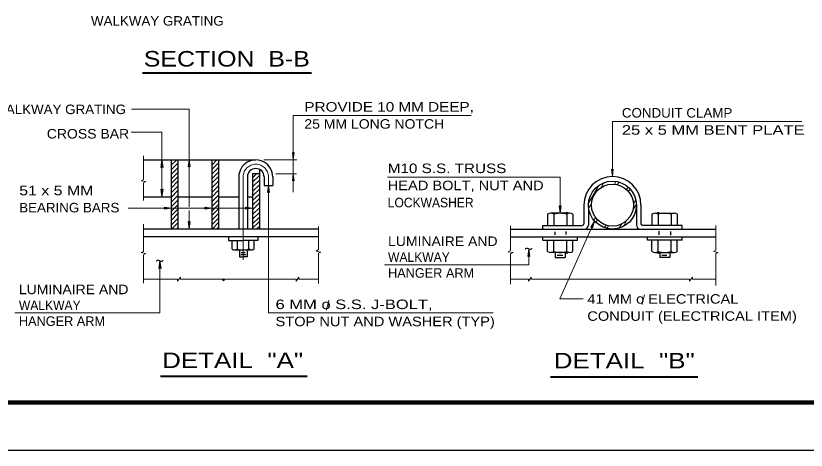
# Model space of a CAD drawing. Extents: x 312601.858 to 312602.699, y 144420.109 to 144420.704.
# Drawn here: x 312602.0138 to 312602.2633, y 144420.1095 to 144420.2465 of the extents above; entities that cross this region are included whole.
import ezdxf
from ezdxf.enums import TextEntityAlignment as Align

# ---------------------------------------------------------------- set-up
doc = ezdxf.new("R2010")
doc.units = 0
doc.header["$LTSCALE"] = 0.0012
doc.header["$PDMODE"] = 32
doc.header["$PDSIZE"] = 0.0006
doc.linetypes.add('DOT_DASHED', pattern=[7.7, 5, -1.2, 0.3, -1.2])
for name, color, linetype, lineweight in [('1', 7, 'Continuous', 13), ('2', 7, 'Continuous', 13), ('39', 7, 'Continuous', 13)]:
    doc.layers.add(name, color=color, linetype=linetype, lineweight=lineweight)

msp = doc.modelspace()

# ---------------------------------------------------------------- hatches: boundary and pattern name
at = {"layer": '39'}
for points in [[(312602.0599, 144420.1989), (312602.0596, 144420.1987), (312602.0599, 144420.2011), (312602.0603, 144420.1987)], [(312602.0599, 144420.1916), (312602.0603, 144420.1918), (312602.0599, 144420.1894), (312602.0596, 144420.1918)], [(312602.1757, 144420.1708), (312602.1754, 144420.1706), (312602.1757, 144420.173), (312602.1761, 144420.1706)], [(312602.1757, 144420.1708), (312602.1754, 144420.1706), (312602.1757, 144420.173), (312602.1761, 144420.1706)], [(312602.1757, 144420.1708), (312602.1754, 144420.1706), (312602.1757, 144420.173), (312602.1761, 144420.1706)], [(312602.0593, 144420.167), (312602.059, 144420.1668), (312602.0593, 144420.1692), (312602.0597, 144420.1668)]]:
    msp.add_hatch(color=256, dxfattribs=at).paths.add_polyline_path(points)

# ---------------------------------------------------------------- linework, layer by layer
at = {"layer": '1'}
for p, q in [((312602.0685, 144420.2171), (312602.0503, 144420.2171)), ((312602.1575, 144420.2151), (312602.1014, 144420.2151)), ((312602.2021, 144420.2132), (312602.2021, 144420.1958)), ((312602.2021, 144420.2132), (312602.2619, 144420.2132)), ((312602.0502, 144420.2098), (312602.0599, 144420.2098)), ((312602.0541, 144420.2023), (312602.0541, 144420.1949)), ((312602.0629, 144420.1994), (312602.0646, 144420.2011)), ((312602.0757, 144420.1994), (312602.0773, 144420.2011)), ((312602.0921, 144420.2011), (312602.1025, 144420.2011)), ((312602.0629, 144420.1979), (312602.065, 144420.2)), ((312602.0629, 144420.1965), (312602.065, 144420.1986)), ((312602.0757, 144420.198), (312602.0778, 144420.2001)), ((312602.0757, 144420.1966), (312602.0778, 144420.1987)), ((312602.0629, 144420.195), (312602.065, 144420.1971)), ((312602.0757, 144420.1951), (312602.0778, 144420.1972)), ((312602.0885, 144420.1954), (312602.0899, 144420.1968)), ((312602.0885, 144420.194), (312602.0907, 144420.1961)), ((312602.0959, 144420.1967), (312602.1024, 144420.1967)), ((312602.1014, 144420.1967), (312602.1014, 144420.1909)), ((312602.0534, 144420.1945), (312602.0541, 144420.1949)), ((312602.0534, 144420.1945), (312602.0549, 144420.1942)), ((312602.0541, 144420.1938), (312602.0549, 144420.1942)), ((312602.0541, 144420.1938), (312602.0541, 144420.1882)), ((312602.0629, 144420.1936), (312602.065, 144420.1957)), ((312602.0629, 144420.1921), (312602.065, 144420.1943)), ((312602.0757, 144420.1937), (312602.0778, 144420.1958)), ((312602.0757, 144420.1922), (312602.0778, 144420.1943)), ((312602.0885, 144420.1926), (312602.0907, 144420.1947)), ((312602.1311, 144420.1956), (312602.1856, 144420.1956)), ((312602.1856, 144420.1956), (312602.1856, 144420.1843)), ((312602.1986, 144420.1923), (312602.1994, 144420.1939)), ((312602.2028, 144420.1934), (312602.2033, 144420.1943)), ((312602.2037, 144420.1933), (312602.2042, 144420.1941)), ((312602.0629, 144420.1907), (312602.065, 144420.1928)), ((312602.0629, 144420.1892), (312602.065, 144420.1914)), ((312602.0757, 144420.1908), (312602.0778, 144420.1929)), ((312602.0757, 144420.1893), (312602.0778, 144420.1915)), ((312602.0885, 144420.1911), (312602.0907, 144420.1932)), ((312602.0885, 144420.1897), (312602.0907, 144420.1918)), ((312602.0936, 144420.193), (312602.0936, 144420.1528)), ((312602.1946, 144420.1874), (312602.1978, 144420.193)), ((312602.2066, 144420.1917), (312602.2071, 144420.1925)), ((312602.2072, 144420.1911), (312602.2077, 144420.1919)), ((312602.0629, 144420.1877), (312602.065, 144420.1898)), ((312602.0757, 144420.1878), (312602.0778, 144420.1899)), ((312602.0885, 144420.1882), (312602.0907, 144420.1903)), ((312602.0885, 144420.1868), (312602.0907, 144420.1889)), ((312602.0629, 144420.1863), (312602.065, 144420.1884)), ((312602.0629, 144420.1848), (312602.065, 144420.1869)), ((312602.0757, 144420.1864), (312602.0778, 144420.1885)), ((312602.0757, 144420.1849), (312602.0778, 144420.187)), ((312602.0885, 144420.1853), (312602.0907, 144420.1875)), ((312602.1931, 144420.1868), (312602.1931, 144420.186)), ((312602.1947, 144420.1858), (312602.1955, 144420.1873)), ((312602.2086, 144420.1852), (312602.2097, 144420.1871)), ((312602.2088, 144420.1872), (312602.2095, 144420.1885)), ((312602.2111, 144420.1868), (312602.2111, 144420.186)), ((312602.0493, 144420.1858), (312602.0629, 144420.1858)), ((312602.0629, 144420.1834), (312602.065, 144420.1855)), ((312602.0629, 144420.1819), (312602.065, 144420.1841)), ((312602.0685, 144420.1851), (312602.0685, 144420.1793)), ((312602.0757, 144420.1858), (312602.0885, 144420.1858)), ((312602.0757, 144420.1835), (312602.0778, 144420.1856)), ((312602.0757, 144420.182), (312602.0778, 144420.1841)), ((312602.0885, 144420.1838), (312602.0907, 144420.1859)), ((312602.0885, 144420.1824), (312602.0907, 144420.1845)), ((312602.0629, 144420.1805), (312602.065, 144420.1826)), ((312602.0631, 144420.1793), (312602.065, 144420.1812)), ((312602.0757, 144420.1806), (312602.0778, 144420.1827)), ((312602.076, 144420.1794), (312602.0778, 144420.1813)), ((312602.0885, 144420.1809), (312602.0907, 144420.183)), ((312602.0885, 144420.1795), (312602.0907, 144420.1816)), ((312602.1965, 144420.1817), (312602.1855, 144420.1572)), ((312602.1963, 144420.182), (312602.1968, 144420.1829)), ((312602.1969, 144420.1814), (312602.1974, 144420.1822)), ((312602.2056, 144420.1801), (312602.2067, 144420.182)), ((312602.0541, 144420.1808), (312602.0541, 144420.1722)), ((312602.0646, 144420.1793), (312602.065, 144420.1797)), ((312602.0774, 144420.1794), (312602.0778, 144420.1798)), ((312602.0898, 144420.1793), (312602.0907, 144420.1801)), ((312602.1094, 144420.1801), (312602.1094, 144420.1728)), ((312602.17, 144420.1803), (312602.17, 144420.1725)), ((312602.1816, 144420.1804), (312602.1856, 144420.1804)), ((312602.1896, 144420.1804), (312602.1875, 144420.1804)), ((312602.1996, 144420.1797), (312602.2001, 144420.1805)), ((312602.2004, 144420.1794), (312602.2009, 144420.1803)), ((312602.2043, 144420.1796), (312602.2051, 144420.1809)), ((312602.2101, 144420.1792), (312602.2088, 144420.1792)), ((312602.2169, 144420.1792), (312602.211, 144420.1792)), ((312602.2146, 144420.1804), (312602.2186, 144420.1804)), ((312602.2204, 144420.1792), (312602.2168, 144420.1792)), ((312602.2226, 144420.1804), (312602.2186, 144420.1804)), ((312602.2348, 144420.1804), (312602.2348, 144420.1726)), ((312602.0821, 144420.1756), (312602.0856, 144420.1756)), ((312602.0891, 144420.1756), (312602.0856, 144420.1756)), ((312602.1816, 144420.1757), (312602.1856, 144420.1757)), ((312602.1896, 144420.1757), (312602.1856, 144420.1757)), ((312602.2146, 144420.1757), (312602.2186, 144420.1757)), ((312602.2226, 144420.1757), (312602.2186, 144420.1757)), ((312602.0534, 144420.1718), (312602.0541, 144420.1722)), ((312602.0534, 144420.1718), (312602.0549, 144420.1715)), ((312602.0541, 144420.1711), (312602.0549, 144420.1715)), ((312602.0541, 144420.1711), (312602.0541, 144420.1622)), ((312602.1086, 144420.1723), (312602.1094, 144420.1728)), ((312602.1086, 144420.1723), (312602.1101, 144420.172)), ((312602.1094, 144420.1716), (312602.1101, 144420.172)), ((312602.1094, 144420.1716), (312602.1094, 144420.1621)), ((312602.1692, 144420.1721), (312602.17, 144420.1725)), ((312602.1692, 144420.1721), (312602.1708, 144420.1718)), ((312602.17, 144420.1714), (312602.1708, 144420.1718)), ((312602.17, 144420.1714), (312602.17, 144420.1619)), ((312602.1757, 144420.173), (312602.1757, 144420.168)), ((312602.234, 144420.1722), (312602.2348, 144420.1726)), ((312602.234, 144420.1722), (312602.2355, 144420.1718)), ((312602.2348, 144420.1715), (312602.2355, 144420.1718)), ((312602.2348, 144420.1715), (312602.2348, 144420.1614)), ((312602.0593, 144420.1692), (312602.0593, 144420.1528)), ((312602.1302, 144420.168), (312602.1757, 144420.168)), ((312602.0649, 144420.1628), (312602.0658, 144420.1641)), ((312602.0658, 144420.1634), (312602.0658, 144420.1641)), ((312602.1023, 144420.1628), (312602.1032, 144420.1641)), ((312602.1032, 144420.1634), (312602.1032, 144420.1641)), ((312602.1756, 144420.1628), (312602.1765, 144420.1641)), ((312602.1765, 144420.1634), (312602.1765, 144420.1641)), ((312602.2264, 144420.1628), (312602.2274, 144420.1641)), ((312602.2274, 144420.1634), (312602.2274, 144420.1641)), ((312602.0541, 144420.1634), (312602.0649, 144420.1634)), ((312602.0649, 144420.1628), (312602.0649, 144420.1634)), ((312602.0658, 144420.1634), (312602.1023, 144420.1634)), ((312602.1023, 144420.1628), (312602.1023, 144420.1634)), ((312602.1032, 144420.1634), (312602.1094, 144420.1634)), ((312602.17, 144420.1634), (312602.1756, 144420.1634)), ((312602.1756, 144420.1628), (312602.1756, 144420.1634)), ((312602.1765, 144420.1634), (312602.2264, 144420.1634)), ((312602.2264, 144420.1628), (312602.2264, 144420.1634)), ((312602.2274, 144420.1634), (312602.2348, 144420.1634)), ((312602.1929, 144420.1572), (312602.1855, 144420.1572)), ((312602.0593, 144420.1528), (312602.0135, 144420.1528)), ((312602.1645, 144420.1528), (312602.0936, 144420.1528))]:
    msp.add_line(p, q, dxfattribs=at)
at = {"layer": '1', "lineweight": 25}
for p, q in [((312602.0541, 144420.2011), (312602.0896, 144420.2011)), ((312602.0629, 144420.2011), (312602.0629, 144420.1793)), ((312602.065, 144420.2011), (312602.065, 144420.1793)), ((312602.0757, 144420.2011), (312602.0757, 144420.1794)), ((312602.0778, 144420.2011), (312602.0778, 144420.1794)), ((312602.0885, 144420.1968), (312602.0907, 144420.1968)), ((312602.0885, 144420.1968), (312602.0885, 144420.1793)), ((312602.0907, 144420.1978), (312602.0907, 144420.1793)), ((312602.0842, 144420.1957), (312602.0842, 144420.1793)), ((312602.0869, 144420.1957), (312602.0869, 144420.1793)), ((312602.0922, 144420.1957), (312602.0922, 144420.193)), ((312602.0949, 144420.1957), (312602.0949, 144420.193)), ((312602.0922, 144420.193), (312602.0949, 144420.193)), ((312602.0541, 144420.1894), (312602.0629, 144420.1894)), ((312602.065, 144420.1894), (312602.0757, 144420.1894)), ((312602.0778, 144420.1894), (312602.0842, 144420.1894)), ((312602.0869, 144420.1894), (312602.0885, 144420.1894)), ((312602.1931, 144420.1867), (312602.1931, 144420.1809)), ((312602.1946, 144420.1868), (312602.1946, 144420.1805)), ((312602.2097, 144420.1868), (312602.2097, 144420.1805)), ((312602.2111, 144420.1868), (312602.2111, 144420.1809)), ((312602.1816, 144420.184), (312602.1816, 144420.1804)), ((312602.1885, 144420.1843), (312602.1827, 144420.1843)), ((312602.1836, 144420.184), (312602.1836, 144420.1804)), ((312602.1877, 144420.184), (312602.1877, 144420.1804)), ((312602.1896, 144420.1839), (312602.1896, 144420.1804)), ((312602.2146, 144420.184), (312602.2146, 144420.1804)), ((312602.2157, 144420.1843), (312602.2216, 144420.1843)), ((312602.2166, 144420.184), (312602.2166, 144420.1804)), ((312602.2207, 144420.184), (312602.2207, 144420.1804)), ((312602.2226, 144420.1839), (312602.2226, 144420.1804)), ((312602.0541, 144420.1793), (312602.1094, 144420.1793)), ((312602.17, 144420.1792), (312602.1841, 144420.1792)), ((312602.1802, 144420.1792), (312602.1802, 144420.1804)), ((312602.1802, 144420.1804), (312602.1926, 144420.1804)), ((312602.1839, 144420.1792), (312602.1874, 144420.1792)), ((312602.1873, 144420.1792), (312602.1933, 144420.1792)), ((312602.1935, 144420.1792), (312602.2348, 144420.1792)), ((312602.2241, 144420.1804), (312602.2117, 144420.1804)), ((312602.2168, 144420.1786), (312602.2168, 144420.1774)), ((312602.2241, 144420.1792), (312602.2241, 144420.1804)), ((312602.0541, 144420.1769), (312602.1094, 144420.1769)), ((312602.081, 144420.1769), (312602.081, 144420.1756)), ((312602.0902, 144420.1769), (312602.0902, 144420.1756)), ((312602.17, 144420.1768), (312602.2348, 144420.1768)), ((312602.1802, 144420.1757), (312602.1802, 144420.1768)), ((312602.1839, 144420.1784), (312602.1839, 144420.1774)), ((312602.1874, 144420.1785), (312602.1874, 144420.1775)), ((312602.1911, 144420.1757), (312602.1911, 144420.1768)), ((312602.2132, 144420.1757), (312602.2132, 144420.1768)), ((312602.2204, 144420.1785), (312602.2204, 144420.1773)), ((312602.2241, 144420.1757), (312602.2241, 144420.1768)), ((312602.081, 144420.1756), (312602.0856, 144420.1756)), ((312602.0821, 144420.1729), (312602.0821, 144420.1756)), ((312602.0838, 144420.1729), (312602.0838, 144420.1756)), ((312602.0902, 144420.1756), (312602.0856, 144420.1756)), ((312602.0874, 144420.1729), (312602.0874, 144420.1756)), ((312602.0891, 144420.1729), (312602.0891, 144420.1756)), ((312602.1802, 144420.1757), (312602.1911, 144420.1757)), ((312602.1816, 144420.1722), (312602.1816, 144420.1757)), ((312602.1836, 144420.1721), (312602.1836, 144420.1757)), ((312602.1877, 144420.1721), (312602.1877, 144420.1757)), ((312602.1896, 144420.1722), (312602.1896, 144420.1757)), ((312602.2241, 144420.1757), (312602.2132, 144420.1757)), ((312602.2146, 144420.1722), (312602.2146, 144420.1757)), ((312602.2166, 144420.1721), (312602.2166, 144420.1757)), ((312602.2207, 144420.1721), (312602.2207, 144420.1757)), ((312602.2226, 144420.1722), (312602.2226, 144420.1757)), ((312602.0821, 144420.1729), (312602.0826, 144420.1727)), ((312602.0826, 144420.1727), (312602.0885, 144420.1727)), ((312602.0844, 144420.1727), (312602.0844, 144420.1705)), ((312602.0848, 144420.1712), (312602.0864, 144420.1712)), ((312602.0849, 144420.1719), (312602.0862, 144420.1719)), ((312602.0891, 144420.1729), (312602.0885, 144420.1727)), ((312602.1885, 144420.1718), (312602.1827, 144420.1718)), ((312602.1841, 144420.1718), (312602.1841, 144420.1703)), ((312602.1872, 144420.1718), (312602.1872, 144420.1703)), ((312602.2157, 144420.1718), (312602.2216, 144420.1718)), ((312602.2171, 144420.1718), (312602.2171, 144420.1703)), ((312602.2202, 144420.1718), (312602.2202, 144420.1703)), ((312602.0844, 144420.1705), (312602.0856, 144420.1705)), ((312602.1841, 144420.1703), (312602.1872, 144420.1703)), ((312602.1847, 144420.171), (312602.1865, 144420.171)), ((312602.2202, 144420.1703), (312602.2171, 144420.1703)), ((312602.2177, 144420.171), (312602.2193, 144420.171))]:
    msp.add_line(p, q, dxfattribs=at)
at = {"layer": '1', "linetype": 'DOT_DASHED'}
for p, q in [((312602.0856, 144420.1695), (312602.0856, 144420.1957)), ((312602.0936, 144420.193), (312602.0936, 144420.1956))]:
    msp.add_line(p, q, dxfattribs=at)
at = {"layer": '1'}
for points in [[(312602.0685, 144420.2171), (312602.0685, 144420.2011), (312602.0685, 144420.1863)], [(312602.1014, 144420.2151), (312602.1014, 144420.2011), (312602.1014, 144420.1967)], [(312602.0599, 144420.2098), (312602.0599, 144420.2011), (312602.0599, 144420.1894)], [(312602.0629, 144420.1858), (312602.0689, 144420.1858), (312602.0757, 144420.1858)]]:
    msp.add_lwpolyline(points, dxfattribs=at)
for points in [[(312602.0682, 144420.1989), (312602.0685, 144420.2011), (312602.0688, 144420.1989), (312602.0685, 144420.1991)], [(312602.1017, 144420.2034), (312602.1014, 144420.2011), (312602.1011, 144420.2034), (312602.1014, 144420.2031)], [(312602.1011, 144420.1945), (312602.1014, 144420.1967), (312602.1017, 144420.1945), (312602.1014, 144420.1947)], [(312602.2024, 144420.1981), (312602.2021, 144420.1958), (312602.2018, 144420.1981), (312602.2021, 144420.1978)], [(312602.0933, 144420.1908), (312602.0936, 144420.193), (312602.0939, 144420.1908), (312602.0936, 144420.191)], [(312602.0607, 144420.1861), (312602.0629, 144420.1858), (312602.0607, 144420.1855), (312602.0609, 144420.1858)], [(312602.0735, 144420.1861), (312602.0757, 144420.1858), (312602.0735, 144420.1855), (312602.0737, 144420.1858)], [(312602.0863, 144420.1861), (312602.0885, 144420.1858), (312602.0863, 144420.1855), (312602.0865, 144420.1858)], [(312602.1859, 144420.1866), (312602.1856, 144420.1843), (312602.1853, 144420.1866), (312602.1856, 144420.1863)], [(312602.0688, 144420.1816), (312602.0685, 144420.1793), (312602.0682, 144420.1816), (312602.0685, 144420.1813)], [(312602.1953, 144420.1798), (312602.1965, 144420.1817), (312602.1958, 144420.1795), (312602.1957, 144420.1799)]]:
    msp.add_lwpolyline(points, close=True, dxfattribs=at)
at = {"layer": '1', "lineweight": 25}
msp.add_lwpolyline([(312602.0868, 144420.1727), (312602.0868, 144420.1705), (312602.0856, 144420.1705)], dxfattribs=at)
for radius in [0.007565, 0.00663]:
    msp.add_circle((312602.20213, 144420.1868), radius, dxfattribs=at)
for centre, radius, start, end in [((312602.08956, 144420.1957), 0.005356, 359.80523, 180.00052), ((312602.08956, 144420.1957), 0.002635, 0.19402, 180), ((312602.20213, 144420.1868), 0.00901, 0, 180), ((312602.19261, 144420.180935), 0.00051, 270, 0), ((312602.19329, 144420.18051), 0.001275, 270, 0), ((312602.21097, 144420.18051), 0.001275, 180, 270), ((312602.21165, 144420.180935), 0.00051, 180, 270), ((312602.08293, 144420.17411), 0.001445, 242.51946, 305.4373), ((312602.085565, 144420.17904), 0.006375, 253.73979, 286.2602), ((312602.0882, 144420.17411), 0.001445, 234.5627, 297.48054)]:
    msp.add_arc(centre, radius, start, end, dxfattribs=at)
at = {"layer": '1', "linetype": 'DOT_DASHED'}
msp.add_arc((312602.08956, 144420.1957), 0.003995, 0.06601, 180, dxfattribs=at)
at = {"layer": '1', "lineweight": 25}
for centre, major_axis, start_param, end_param in [((312602.182638, 144420.182775), (0.001722, 0), 0.970898, 2.1858445), ((312602.185632, 144420.178399), (0.006971, 0), 1.2763403, 1.8649531), ((312602.188626, 144420.182775), (0.001722, 0), 0.9448732, 2.1695573), ((312602.215634, 144420.182775), (-0.001722, 0), 4.113628, 5.3383121), ((312602.218628, 144420.178399), (-0.006971, 0), 4.4182323, 5.006845), ((312602.221622, 144420.182775), (-0.001722, 0), 4.0973408, 5.3122873), ((312602.182638, 144420.173315), (0.001722, 0), 4.0973408, 5.3122873), ((312602.185632, 144420.177691), (0.006971, 0), 4.4182323, 5.006845), ((312602.188626, 144420.173315), (0.001722, 0), 4.113628, 5.3383121), ((312602.215634, 144420.173315), (-0.001722, 0), 0.9448732, 2.1695573), ((312602.218628, 144420.177691), (-0.006971, 0), 1.2763403, 1.8649531), ((312602.221622, 144420.173315), (-0.001722, 0), 0.970898, 2.1858445)]:
    msp.add_ellipse(centre, major_axis=major_axis, ratio=0.83375, start_param=start_param, end_param=end_param, dxfattribs=at)
at = {"layer": '1'}
for centre, major_axis, ratio, start_param, end_param in [((312602.185558, 144420.175973), (-0.009881, 0), 0.83375, 4.4986502, 4.498801), ((312602.191695, 144420.175973), (0.009881, 0), 0.83375, 1.7843843, 1.7845351), ((312602.212565, 144420.175973), (-0.009881, 0), 0.83375, 4.4986502, 4.5023266), ((312602.218702, 144420.175973), (0.009881, 0), 0.83375, 1.7843843, 1.7845351), ((312602.085519, 144420.17911), (-0.008631, 0), 0.74025, 1.7843843, 1.7845351), ((312602.090881, 144420.17911), (0.008631, 0), 0.74025, 4.4986502, 4.498801), ((312602.185558, 144420.180117), (-0.009881, 0), 0.83375, 1.7843843, 1.7845351)]:
    msp.add_ellipse(centre, major_axis=major_axis, ratio=ratio, start_param=start_param, end_param=end_param, dxfattribs=at)
for p in [(312602.1877, 144420.1843), (312602.2166, 144420.1843), (312602.0874, 144420.1728), (312602.1877, 144420.1718), (312602.2166, 144420.1718), (312602.0794, 144420.1632)]:
    msp.add_point(p, dxfattribs=at)
at = {"layer": '2', "lineweight": 40}
for p, q in [((312602.0538, 144420.2285), (312602.1071, 144420.2285)), ((312602.0595, 144420.1328), (312602.1058, 144420.1328)), ((312602.1826, 144420.1326), (312602.2291, 144420.1326))]:
    msp.add_line(p, q, dxfattribs=at)
at = {"layer": '2'}
for points in [[(312602.1747, 144420.1728), (312602.1748, 144420.1731), (312602.175, 144420.1732), (312602.1752, 144420.1732), (312602.1755, 144420.1731), (312602.1756, 144420.1731), (312602.1757, 144420.173), (312602.1758, 144420.173), (312602.1759, 144420.1729), (312602.1761, 144420.1729), (312602.1762, 144420.1728), (312602.1763, 144420.1728), (312602.1765, 144420.1729), (312602.1766, 144420.1729), (312602.1766, 144420.173), (312602.1767, 144420.1731), (312602.1767, 144420.1732)], [(312602.0582, 144420.169), (312602.0583, 144420.1693), (312602.0585, 144420.1694), (312602.0587, 144420.1694), (312602.059, 144420.1693), (312602.0591, 144420.1693), (312602.0592, 144420.1692), (312602.0593, 144420.1692), (312602.0594, 144420.1691), (312602.0596, 144420.1691), (312602.0597, 144420.169), (312602.0598, 144420.169), (312602.06, 144420.1691), (312602.0601, 144420.1691), (312602.0601, 144420.1692), (312602.0602, 144420.1693), (312602.0602, 144420.1694)]]:
    msp.add_spline(points, degree=3, dxfattribs=at)
at = {"layer": '39', "lineweight": 25}
msp.add_lwpolyline([(312601.8578, 144420.1095), (312602.6988, 144420.1095), (312602.6988, 144420.7035)], dxfattribs=at)
at = {"layer": '39', "lineweight": 158}
msp.add_lwpolyline([(312601.9088, 144420.1245), (312602.6838, 144420.1245), (312602.6838, 144420.6645)], dxfattribs=at)
at = {"layer": '39'}
for points in [[(312602.0599, 144420.1989), (312602.0596, 144420.1987), (312602.0599, 144420.2011), (312602.0603, 144420.1987)], [(312602.0599, 144420.1916), (312602.0603, 144420.1918), (312602.0599, 144420.1894), (312602.0596, 144420.1918)], [(312602.1757, 144420.1708), (312602.1754, 144420.1706), (312602.1757, 144420.173), (312602.1761, 144420.1706)], [(312602.1757, 144420.1708), (312602.1754, 144420.1706), (312602.1757, 144420.173), (312602.1761, 144420.1706)], [(312602.1757, 144420.1708), (312602.1754, 144420.1706), (312602.1757, 144420.173), (312602.1761, 144420.1706)], [(312602.0593, 144420.167), (312602.059, 144420.1668), (312602.0593, 144420.1692), (312602.0597, 144420.1668)]]:
    msp.add_lwpolyline(points, close=True, dxfattribs=at)

# ---------------------------------------------------------------- texts
at = {"layer": '2', "width": 1.05}
msp.add_text('WALKWAY GRATING', height=0.003, dxfattribs=at).set_placement((312602.0585, 144420.2434), align=Align.CENTER)
at = {"layer": '2'}
for s, height, width, p in [('SECTION  B-B', 0.0049, 1.2, (312602.0542, 144420.2305)), ('WALKWAY GRATING', 0.003, 1.05, (312602.0067, 144420.2155)), ('PROVIDE 10 MM DEEP, ', 0.003, 1.2, (312602.1049, 144420.2163)), ('CONDUIT CLAMP', 0.003, 1.05, (312602.2051, 144420.2144)), ('25 MM LONG NOTCH', 0.003, 1.1, (312602.1049, 144420.2109)), ('25 x 5 MM BENT PLATE', 0.003, 1.3, (312602.2051, 144420.209)), ('CROSS BAR', 0.003, 1.1, (312602.0236, 144420.2078)), ('M10 S.S. TRUSS', 0.003, 1.2, (312602.1312, 144420.1969)), ('HEAD BOLT, NUT AND', 0.003, 1.15, (312602.1312, 144420.1915)), ('51 x 5 MM', 0.003, 1.25, (312602.0149, 144420.1899)), ('LOCKWASHER', 0.003, 0.95, (312602.1312, 144420.1861)), ('BEARING BARS', 0.003, 1.05, (312602.0149, 144420.1845)), ('LUMINAIRE AND', 0.003, 1.1, (312602.1313, 144420.1739)), ('WALKWAY', 0.003, 0.95, (312602.1313, 144420.1689)), ('LUMINAIRE AND', 0.003, 1.1, (312602.0148, 144420.1587)), ('41 MM o ELECTRICAL', 0.003, 1.15, (312602.1942, 144420.1557)), ('WALKWAY', 0.003, 0.95, (312602.0148, 144420.1537)), ('6 MM o S.S. J-BOLT,', 0.003, 1.3, (312602.0958, 144420.154)), ('STOP NUT AND WASHER (TYP)', 0.003, 1.15, (312602.0958, 144420.1486)), ('CONDUIT (ELECTRICAL ITEM)', 0.003, 1.15, (312602.1942, 144420.1503)), ('DETAIL  "A"', 0.0049, 1.25, (312602.06, 144420.1354)), ('DETAIL  "B"', 0.0049, 1.25, (312602.1836, 144420.1353))]:
    msp.add_text(s, height=height, dxfattribs=dict(at, width=width)).set_placement(p)
for p in [(312602.1313, 144420.1639), (312602.0148, 144420.1487)]:
    msp.add_text('HANGER ARM', height=0.003, dxfattribs=at).set_placement(p)
for p in [(312602.11225, 144420.1537), (312602.21185, 144420.1554)]:
    msp.add_text('/', height=0.003, dxfattribs=at).set_placement(p, align=Align.CENTER)

doc.saveas('drawing.dxf')
